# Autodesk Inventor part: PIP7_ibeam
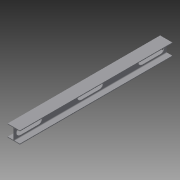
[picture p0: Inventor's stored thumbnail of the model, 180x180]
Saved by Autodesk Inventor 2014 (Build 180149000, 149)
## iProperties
Shininess: 64.0
Length Units: 11272
Angle Units: 11279
Time Units: 11290
Mass Units: 11286
Length Display Precision: 3
Angle Display Precision: 2
Compacted: True
Part Number: PIP7_ibeam
Document SubType Name: Modeling
Created: 2003-01
Designer: dayb
Density: 1 g/cm^3
Mass: 269.364 g
Surface Area: 1701.34 cm^2
Volume: 269.364 cm^3
Material: Generic
Appearance: Default
Density: 0.0
Volumn: 0.0
Area: 0.0
PropertySet Name: Model Information
Control State: 0
Master: False
Checked Out: False
Author: dayb
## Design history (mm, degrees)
sketch "Sketch1"
  geometry: L1 (-43.459, 37.881)-(7.341, 37.881); L2 (7.341, 37.881)-(7.341, 34.706); L3 (7.341, 34.706)-(-16.472, 34.706); L4 (-16.472, 34.706)-(-16.472, -9.744); L5 (-16.472, -9.744)-(7.341, -9.744); L6 (7.341, -9.744)-(7.341, -12.919); L7 (7.341, -12.919)-(-43.459, -12.919); L8 (-43.459, -12.919)-(-43.459, -9.744); L9 (-43.459, -9.744)-(-19.647, -9.744); L10 (-19.647, -9.744)-(-19.647, 34.706); L11 (-19.647, 34.706)-(-43.459, 34.706); L12 (-43.459, 34.706)-(-43.459, 37.881)
  constraints: 24 end point, 9 parallel, 6 equal length, 5 collinear, 1 horizontal, 1 perpendicular
  dimensions: "d0" = 50.8 distance of L1.start L1.end; "d1" = 50.8 distance between parallel lines of L7 L1 (= d0); "d2" = 3.175 distance between parallel lines of L10 L4 (= d3); "d3" = 3.175 distance of L1.end L2.end
extrude "Extrusion1" new body sketch "Sketch1" distance "d4" = 635; taper "d5" = 0 deg
sketch "Sketch2"
  geometry: L1 (-635, 44.45)-(-635, 0) reference; L2 (0, 47.625)-(-635, 47.625) reference; L3 (-609.6, 38.1)-(-533.4, 38.1); L4 (-533.4, 6.35)-(-609.6, 6.35); A1 r 15.875 centre (-609.6, 22.225) between (-609.6, 38.1) and (-609.6, 6.35); A2 r 15.875 centre (-533.4, 22.225) between (-533.4, 6.35) and (-533.4, 38.1)
  constraints: 5 point on circle, 4 end point, 2 centre point, 2 parallel, 2 tangent, 1 point on line
  dimensions: "d6" = 25.4 distance from line of L2 A1.centre (= 0.5 x d1); "d7" = 25.4 distance from line of L2 A2.centre (= d6); "d8" = 31.75 diameter of A1; "d9" = 31.75 diameter of A2; "d10" = 25.4 distance from line of L1 A1.centre; "d11" = 76.2 distance of L3.start L3.end
extrude "Extrusion2" cut sketch "Sketch2" stored distance "d12" = 635; taper "d13" = 0 deg
pattern_linear "Rectangular Pattern1" dims "d16" = 254
fillet "Fillet1" dims "d17" = 3.175
body "Solid1"
